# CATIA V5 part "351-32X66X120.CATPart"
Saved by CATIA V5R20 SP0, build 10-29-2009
Part number: 351-32X66X120
Definition: NONE
Nomenclature: 351-32X66X120
Source: Unknown
Description: 351-32X66X120
Bounding box of the stored display mesh (mm): x -7 to 113, y -22.5 to 22.5, z -22.5 to 22.5
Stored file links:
  C:\Users\Utente\Desktop\IO LAVORO\3D X SITO CF\X SITO\PLASTICA\351\351-32X66X120.CATPart
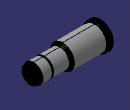
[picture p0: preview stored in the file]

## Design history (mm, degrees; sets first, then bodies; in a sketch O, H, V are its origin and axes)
Body1 "351-32X66X120" (main body)
  Solid1: solid without history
